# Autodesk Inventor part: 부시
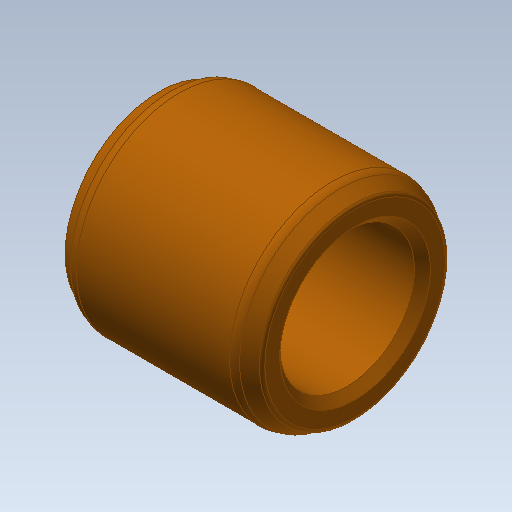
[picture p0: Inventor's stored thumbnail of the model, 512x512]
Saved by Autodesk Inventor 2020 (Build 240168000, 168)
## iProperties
Created: 2018-11
Part Number: 부시
Material: 강철, 연강
Document SubType Name: Modeling
Designer: mduedu
Density: 1 g/cm^3
Appearance: 주황색
Author: mduedu
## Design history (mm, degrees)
sketch "스케치1"
  geometry: C1 r 8.5 at (0, 0); C2 r 13 at (0, 0); 1 further point
  constraints: 2 centre point, 2 coincident
  dimensions: "d0" = 17 diameter of C1; "d1" = 26 diameter of C2
extrude "돌출1" new body sketch "스케치1" distance "d2" = 25; taper "d3" = 0 deg
chamfer "모따기4" distance "d14" = 1; stored, may be unused: second distance "d15" = 2, angle "d16" = 15 deg
chamfer "모따기5" distance "d17" = 2.3; stored, may be unused: second distance "d18" = 2, angle "d19" = 30 deg
chamfer "모따기6" distance "d20" = 2.3; stored, may be unused: second distance "d21" = 2, angle "d22" = 30 deg
fillet "모깎기2" dims "d23" = 2, "d24" = 0.5
fillet "모깎기3" dims "d25" = 2, "d26" = 0.5
node "솔리드1"
